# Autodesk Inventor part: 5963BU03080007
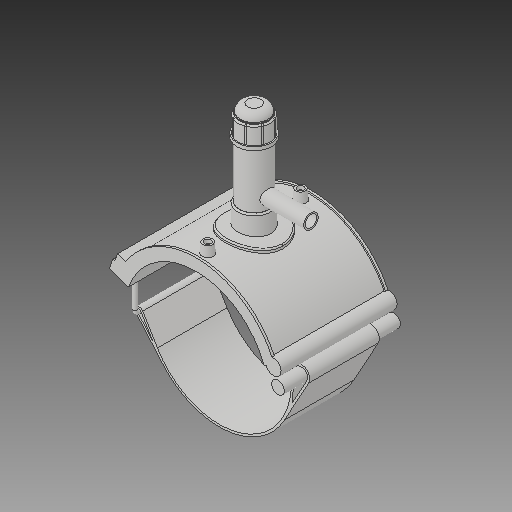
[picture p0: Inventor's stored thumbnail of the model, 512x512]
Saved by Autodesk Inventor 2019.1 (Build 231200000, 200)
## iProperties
Created: 2017-07
Part Number: 5963BU03080007
Material: Generic
Description: PLASSON TAPPING SADDLE 8''IPS x 1 3/4''CTS
Document SubType Name: Modeling
Designer: KIM
Mass: 1712.7 g
Surface Area: 2671.49 cm^2
Volume: 1712.7 cm^3
Density: 1 g/cm^3
Appearance: Default
Author: KIM
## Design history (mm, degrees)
derived "5963B.ipt"
feature "Solid1::5963B.ipt"
feature "Solid2::5963B.ipt"
feature "Solid4::5963B.ipt"
feature "Solid5::5963B.ipt"
tag "TaggingFeature1" dims "d6" = 0.1
body "Solid1"
body "Solid2"
other parameters: "d0" = 218.7, "d2" = 269.748, "d3" = 54.675, "d4" = 176.022, "d5" = 0, "d8" = 0, "d19" = 6, "d20" = 6, "d21" = 105.6132, "d23" = 0, "d24" = 52.8066, "d26" = 0, "d29" = 3, "d30" = 72.9, "d31" = 6, "d32" = 0, "d33" = 0, "d34" = 0.6, "d40" = 129.64536, "d41" = 87.48, "d43" = 0, "d45" = 0, "d47" = 230.2722, "d70" = 15, "d72" = 0, "d73" = 6, "d75" = 5, "d76" = 0, "d77" = 10.935, "d78" = 139.35, "d79" = 15, "d80" = 70.4088, "d82" = 5 deg, "d84" = 4, "d85" = 14, "d86" = 0, "d87" = 3, "d88" = 0, "d89" = 1, "d90" = 1, "d91" = 140.8176, "d92" = 0, "d93" = 0.5, "d94" = 115.10526, "d96" = 254.30436, "d97" = 3.52044, "d98" = 0, "d102" = 2.187, "d120" = 140 deg, "d121" = 24.228, "d122" = 20 deg, "d123" = 498.636, "d124" = 149.5908, "d126" = 0, "d143" = 225.261, "d145" = 23.55231, "d149" = 3.2805, "d150" = 25.90754, "d153" = 176.022, "d154" = 0, "d156" = 124.659, "d157" = 160 deg, "d159" = 6.1236, "d161" = 3.2805, "d162" = 105.6132, "d163" = 0, "d164" = 109.35, "d167" = 21.87, "d168" = 121.61854, "d170" = 3.2805, "d172" = 0, "d173" = 1, "d175" = 109.35, "d176" = 20 deg, "d177" = 15.309, "d178" = 30.618, "d180" = 0, "d183" = 12.2472, "d184" = 12.2472, "d185" = 57.20715, "d186" = 57.20715, "d187" = 124.659, "d188" = 9.1854, "d189" = 15.309, "d190" = 0, "d191" = 186.9885, "d193" = 6.1236, "d194" = 6.16077, "d195" = 90 deg, "d197" = 0, "d199" = 0, "d200" = 15.309, "d202" = 0, "d203" = 177.038, "d204" = 49.8636, "d205" = 36.7416, "d206" = 44.6148, "d207" = 132.7785, "d208" = 138.08964, "d209" = 164.64534, "d210" = 45.13968, "d211" = 52.488, "d212" = 41.9904, "d213" = 48.5766, "d216" = 0, "d217" = 21.87, "d218" = 10.935, "d219" = 2.187, "d222" = 218.7, "d224" = 0, "d230" = 2.187, "d233" = 6, "d236" = 89.916, "d237" = 52.8066, "d238" = 6.02433, "d240" = 52.8066, "d241" = 52.8066, "d242" = 52.8066, "d243" = 6, "d244" = 52.8066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
